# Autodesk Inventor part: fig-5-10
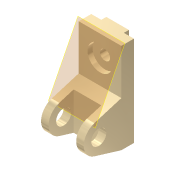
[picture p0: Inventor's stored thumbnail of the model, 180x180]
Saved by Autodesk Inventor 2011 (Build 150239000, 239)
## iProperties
Shininess: 65.0
Angle Display Precision: 2
Document Length Units: 11269
Document Angle Units: 11279
Document Time Units: 11290
Document Mass Units: 11283
Document Length Units Precision: 3
Document Angle Units Precision: 2
Compacted: False
Created: 2001-11
Part Number: fig-5-10
Document SubType Name: Modeling
Designer: Renu Muthoo
Density: 1 g/cm^3
Density: 0.0
Volumn: 0.0
Area: 0.0
PropertySet Name: Model Information
Control State: 0
Master: False
Checked Out: False
Author: Renu Muthoo
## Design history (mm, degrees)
node "Sketch1"
sketch "Sketch2"
  geometry: L1 (33.257, 104.664)-(33.257, -75.336); L2 (33.257, -75.336)-(8.257, -75.336); L3 (8.257, -75.336)-(-45.451, -59.045); L4 (-45.451, -1.628)-(8.257, 14.664); L5 (8.257, 14.664)-(8.257, 104.664); L6 (8.257, 104.664)-(33.257, 104.664); C1 r 15 at (-36.743, -30.336); A1 r 30 centre (-36.743, -30.336) between (-45.451, -1.628) and (-45.451, -59.045)
  constraints: 12 end point, 2 centre point, 2 equal length, 2 parallel, 2 point on circle, 2 tangent, 1 coincident, 1 perpendicular, 1 vertical
  dimensions: "d0" = 180 distance of L1.start L1.end; "d1" = 30 radius of A1; "d2" = 25 distance of L5.end L1.start; "d3" = 45 distance from line of L2 A1.centre; "d4" = 70 distance from line of L1 A1.centre; "d5" = 30 diameter of C1
extrude "Extrusion1" new body sketch "Sketch2" distance "d6" = 85; taper "d7" = 0 deg
workplane "Work Plane1"
sketch "Sketch3"
  geometry: L1 (15, 62.364)-(70, 62.364); L2 (70, 62.364)-(70, -52.386); L3 (70, -52.386)-(15, -52.386); L4 (15, -52.386)-(15, 62.364); L5 (0, -45)-(0, -28.708) reference
  constraints: 8 end point, 2 parallel, 1 horizontal, 1 perpendicular
  dimensions: "d8" = 55 distance of L1.start L1.end; "d9" = 15 distance between parallel lines of L5 L4
extrude "Extrusion2" cut sketch "Sketch3" distance "d10" = 50; taper "d11" = 0 deg
sketch "Sketch4"
  geometry: L1 (0, 25)-(85, 25) reference; L2 (0, 0)-(0, 25) reference; L3 (20, 25)-(65, 25); L4 (65, 25)-(65, 35); L5 (65, 35)-(20, 35); L6 (20, 35)-(20, 25)
  constraints: 8 end point, 2 parallel, 1 horizontal, 1 perpendicular, 1 point on line
  dimensions: "d12" = 45 distance of L4.end L5.end; "d13" = 10 distance of L3.end L4.end; "d14" = 20 distance between parallel lines of L2 L6
extrude "Extrusion3" join sketch "Sketch4" stored distance "d15" = 50; taper "d16" = 0 deg
sketch "Sketch5"
  geometry: L1 (85, 0)-(85, 90) reference; L2 (0, 90)-(85, 90) reference; 1 further point
  dimensions: "d17" = 42 distance from line of L2 point (42.5, 48); "d18" = 42.5 distance from line of L1 point (42.5, 48)
hole "Hole1" sketch "Sketch5" at (42.5, 48) diameter "d19" = 20; stored, may be unused: countersink angle "d23" = 82 deg, drill point angle "d25" = 118 deg; dims "d20" = 6, "d21" = 50, "d22" = 10, "d24" = 8
workplane "Work Plane4"
body "Solid1"
